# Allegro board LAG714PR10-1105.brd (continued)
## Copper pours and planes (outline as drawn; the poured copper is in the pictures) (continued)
AUD_SPK_R+_C on TOP (solid shape): 26.31,3.2 26.31,2.37 26.26,2.32 25.66,2.32 25.34,2.65 24.51,2.65 23.62,1.76 21.18,1.76 21.08,1.86 21.08,2.51 21.19,2.62 21.29,2.62 21.51,2.66 21.7,2.77 22.42,2.77 22.93,3.28 26.23,3.28
AUD_SPK_R+_C on BOTTOM (solid shape): 17.53,6.2 20.58,6.2 21.41,5.37 21.41,3.11 22.26,2.26 22.26,1.84 21.99,1.57 21.04,1.57 20.28,2.33 20.28,4.8 19.89,5.19 19.88,5.19 19.8,5.27 16.15,5.27 16.12,5.29 16.12,6.66 16.17,6.71 17.02,6.71
AUD_SPK_R- on TOP (solid shape): 27.96,4.06 27.97,4.06 28.1,3.93 31.09,3.93 31.35,3.67 31.35,3.25 31.02,2.92 27.78,2.92 27.3,3.4 26.61,3.4 26.49,3.52 26.49,4.28 26.57,4.36 27.66,4.36
AUD_SPK_R- on TOP (solid shape): 30.55,10.6 30.55,9.27 30.69,9.13 30.74,9.06 30.8,9.01 31.09,8.72 31.15,8.63 31.24,8.57 31.24,8.38 31.12,8.25 30.93,8.25 30.29,8.89 30.29,10.6 30.36,10.66 30.48,10.66
AUD_SPK_R- on IN2 (solid shape): 31.37,4.35 31.37,3.33 31.21,3.17 30.39,3.17 30.1,3.46 30.1,4.6 30.26,4.76 30.96,4.76
AUD_SPK_R- on IN2 (solid shape): 31.12,8.68 31.15,8.64 31.18,8.61 31.18,7.58 30.96,7.36 30.2,7.36 30.07,7.49 30.07,9.08 30.26,9.27 30.52,9.27
AUD_SPK_R-_C on TOP (solid shape): 21.3,4.83 23.47,4.83 24.13,4.17 25.34,4.17 25.48,4.31 26.3,4.31 26.31,4.3 26.31,3.54 26.28,3.51 25.75,3.51 25.68,3.58 22.56,3.58 22.19,3.95 18.67,3.95 18.49,4.14 18.49,5.05 18.56,5.12 21.01,5.12
AUD_SPK_R-_C on BOTTOM (solid shape): 15.74,6.46 15.74,5.13 15.99,4.88 19.64,4.88 19.89,4.64 19.89,4.29 19.42,3.82 16.04,3.82 15.63,4.22 15.63,4.43 15.08,4.99 15.08,6.53 15.2,6.65 15.55,6.65
BST_1.2V on BOTTOM (solid shape): 95.8,137 95.8,136.63 95.83,136.61 95.83,136.52 95.8,136.5 95.8,135.99 95.2,135.38 95.2,133.93 95.14,133.88 95.04,133.88 94.99,133.93 94.99,134.73 94.94,134.78 94.94,136.85 95.11,137.02 95.79,137.02
BST_1.2V_R on BOTTOM (solid shape): 94.41,137 94.41,136.14 94.38,136.11 93.67,136.11 93.44,136.34 92.83,136.34 92.82,136.36 92.82,136.85 92.99,137.02 94.4,137.02
BST_3V on BOTTOM (solid shape): 105.62,138.62 106.78,138.62 106.84,138.55 106.84,138.43 106.78,138.36 106.33,138.36 105.13,137.16 104.24,137.16 104.24,137.86 105.08,138.7 105.54,138.7
BST_5V on BOTTOM (solid shape): 155.99,137.09 157.07,137.09 157.13,137.03 157.13,136.9 157.02,136.79 153.91,136.79 153.81,136.89 153.81,137.4 153.88,137.47 155.61,137.47
BST_+1VALW on BOTTOM (solid shape): 166.47,54.84 166.47,54.65 165.83,54.02 165.83,52.87 166.15,52.56 166.15,51.98 165.26,51.98 165.26,54.46 165.71,54.91 166.4,54.91
BST_+1VALW_R on BOTTOM (solid shape): 166.15,50.59 164.44,50.59 164.31,50.71 164.31,51.2 164.33,51.22 166.15,51.22
BST_VCCSA on BOTTOM (solid shape): 172.06,62.29 171.92,62.15 171.92,62.02 171.87,61.97 171.74,61.97 171.19,61.43 170.32,61.43 170.21,61.53 170.21,61.83 170.34,61.95 170.85,61.95 171.42,62.53 171.42,63.22 172.06,63.22
BST_VCORE1 on BOTTOM: 163.35,76.9 162.54,76.9 162.47,76.83 162.47,76.65 162.52,76.6 163.41,76.6 163.47,76.54 164.63,76.54 164.65,76.56 164.65,77.44 164.63,77.47 163.91,77.47
BST_VCORE1_R on BOTTOM (solid shape): 166.1,77.44 166.1,75.41 166.04,75.34 165.36,75.34 165.32,75.38 165.32,77.38 165.33,77.43 165.36,77.47 166.07,77.47
BST_VCORE2 on BOTTOM: 162.45,98.92 162.16,99.2 161.32,99.2 161.25,99.13 161.25,98.95 161.32,98.87 161.75,98.87 161.75,98.87 161.8,98.87 162.4,98.27 162.4,98.22 162.61,98.01 163.29,98.01 163.31,98.03 163.31,98.89 163.28,98.92
BST_VCORE2_R on BOTTOM (solid shape): 164.73,98.86 164.73,96.92 164.63,96.82 163.99,96.82 163.93,96.88 163.93,98.85 163.99,98.91 164.68,98.91
BST_VGT1 on BOTTOM (solid shape): 140.24,132.65 141.13,132.65 141.19,132.58 141.19,132.39 141.13,132.33 139.99,132.33 139.73,132.08 139.1,132.08 139.1,132.96 139.92,132.96
BST_VGT1_R on BOTTOM (solid shape): 138.34,132.08 137.7,132.08 137.7,134.17 138.34,134.17
HDMI_PLL_GND on TOP (solid shape): 16.77,101.69 16.77,96.16 16.34,95.73 14.62,95.73 14.36,95.99 14.36,99.95 16.16,101.76 16.7,101.76
IR_GND on BOTTOM (solid shape): 212.95,49.08 212.95,48.32 212.89,48.26 211.93,48.26 211.81,48.38 211.81,49.02 211.93,49.14 212.89,49.14
LG_1.2V on BOTTOM (solid shape): 94,133.64 94,133.53 93.92,133.46 93.16,133.46 92.31,134.31 92.31,134.56 92.4,134.65 92.98,134.65
LG_1.2V on IN2 (solid shape): 90.9,138.17 90.9,136.55 90.88,136.52 90.2,136.52 90.08,136.65 90.08,136.96 90.33,137.22 90.33,138.17 90.46,138.3 90.78,138.3
LG_1.2V on IN2 (solid shape): 93.25,134.34 93.25,133.87 93.15,133.76 92.85,133.76 92.25,134.36 91.98,134.36 91.6,134.74 91.6,134.93 91.98,135.31 92.27,135.31
LGATE_CHG on BOTTOM (solid shape): 191.3,45.52 191.3,45.27 191.17,45.14 189.14,45.14 189.01,45.27 189.01,45.59 189.07,45.65 191.17,45.65
LGATE_CHG on BOTTOM (solid shape): 197.58,50.99 198.73,50.99 198.78,50.94 198.78,50.77 198.74,50.73 197.77,50.73 197.52,50.83 197.27,50.73 196.44,50.73 196.31,50.86 196.31,51.11 196.44,51.24 197.33,51.24
LGATE_CHG on IN2 (solid shape): 192.5,45.72 192.5,45.46 192.19,45.14 190.28,45.14 190.15,45.27 190.15,45.52 190.28,45.65 191.55,45.65 191.8,45.91 192.31,45.91
LGATE_CHG on IN2 (solid shape): 197.46,51.11 197.46,50.83 197.32,50.77 197.22,50.67 197.01,50.67 196.38,50.03 196.06,50.03 195.74,50.35 195.74,50.54 196.44,51.24 197.33,51.24
LX_1.2V on TOP (solid shape): 87.28,139.16 87.28,137.56 87.19,137.47 85.63,137.47 85.51,137.6 85.51,139.12 85.63,139.25 87.19,139.25
LX_1.2V on BOTTOM (solid shape): 89.89,140.14 92.93,140.14 92.93,139.06 90.33,139.06 88.74,137.47 84.49,137.47 83.92,138.04 83.92,141.35 84.17,141.6 88.43,141.6
LX_1.2V on BOTTOM (solid shape): 93.44,135.92 93.44,135.67 94.4,134.72 94.4,133.92 94.34,133.87 94.24,133.87 92.74,135.36 92.74,135.89 92.81,135.95 93.42,135.95
LX_1.2V on IN2 (solid shape): 91.09,139.95 91.09,139.5 90.97,139.38 89.19,139.38 89.06,139.5 89.06,139.95 89.25,140.14 90.9,140.14
LX_1.2V on IN2 (solid shape): 93.76,135.89 93.76,135.06 94.08,134.74 94.08,134.49 93.95,134.36 93.7,134.36 93,135.06 93,135.89 93.13,136.01 93.63,136.01
LX_1.8VALW on TOP (solid shape): 163.04,47.98 163.74,47.29 163.74,46.46 163.61,46.33 161.64,46.33 161.39,46.59 161.39,48.68 163.04,48.68
LX_1.8VALW on BOTTOM (solid shape): 163.42,48.05 163.42,47.6 163.8,47.22 165.13,47.22 165.2,47.16 165.2,46.52 165.13,46.46 164.25,46.46 164.12,46.33 164.12,45.63 163.86,45.37 160.89,45.37 160.85,45.41 160.85,48.14 160.89,48.17 163.29,48.17
LX_3V on TOP (solid shape): 107.6,136.33 107.6,134.87 107.54,134.81 105.89,134.81 105.83,134.87 105.83,136.27 106.08,136.52 107.41,136.52
LX_3V on BOTTOM (solid shape): 107.62,138.22 107.62,131.14 107.29,130.81 103.86,130.81 103.09,131.57 103.09,135.25 103.22,135.38 105.38,135.38 106.02,136.01 106.02,137.41 106.9,138.3 107.54,138.3
LX_3V on BOTTOM (solid shape): 106.97,142.17 106.97,141.73 107.16,141.54 107.16,140.52 107.1,140.46 106.97,140.46 106.33,141.09 106.33,141.73 106.46,141.85 106.46,142.24 106.59,142.36 106.78,142.36
LX_3V on IN2 (solid shape): 106.99,142.21 107.02,142.09 107.1,141.99 107.1,139.06 107.64,138.51 107.64,136.81 107.54,136.71 106.63,136.71 106.52,136.81 106.52,138.11 106.08,138.55 106.08,142.17 106.27,142.36 106.84,142.36
LX_5V on TOP (solid shape): 157.77,134.34 157.77,133.15 157.64,133.03 155.48,133.03 155.23,133.28 155.23,134.17 155.48,134.42 157.68,134.42
LX_5V on BOTTOM (solid shape): 157.51,140.33 157.51,139 157.45,138.93 157.26,138.93 157.2,139 157.2,139.63 157.01,139.82 156.56,139.82 156.43,139.95 156.43,140.39 156.5,140.46 157.39,140.46
LX_5V on BOTTOM (solid shape): 157.96,136.65 157.96,135.25 158.53,134.68 160,134.68 160.18,134.5 160.18,132.2 160.05,132.08 155.61,132.08 155.04,132.65 155.04,134.98 155.18,135.12 155.61,135.12 157.26,136.77 157.83,136.77
LX_5V on IN2 (solid shape): 157.64,140.33 157.64,135.19 157.45,135 156.63,135 156.43,135.19 156.43,140.33 156.56,140.46 157.51,140.46
LX_+1VALW on TOP (solid shape): 165.01,56.3 165.01,55.1 164.75,54.84 162.78,54.84 162.78,56.49 164.82,56.49
LX_+1VALW on BOTTOM (solid shape): 167.02,56.96 167.02,55.39 166.91,55.29 165.77,55.29 164.88,54.4 164.88,51.6 164.34,51.6 164.31,51.63 164.31,52.62 163.86,53.07 162,53.07 161.96,53.11 161.96,56.87 162.28,57.19 166.79,57.19
LX_VCCSA on TOP (solid shape): 163.74,63.3 163.74,62.29 163.61,62.16 161.64,62.16 161.39,62.42 161.39,63.5 161.45,63.56 163.48,63.56
LX_VCCSA on BOTTOM (solid shape): 164.25,62.73 166.99,62.73 167.56,63.3 168.25,63.3 168.31,63.24 168.31,62.35 168.06,62.1 168.06,61.34 168.18,61.21 168.94,61.21 169.01,61.15 169.01,61.02 168.88,60.89 167.86,60.89 167.04,61.72 164.05,61.72 163.6,61.26 163.6,60.49 163.11,60 161.13,60 160.88,60.26 160.88,61.46 160.94,61.53 161.9,61.53 161.9,62.42 160.94,62.42 160.88,62.48 160.88,63.43 161.01,63.56 163.42,63.56
LX_VCORE1 on TOP (solid shape): 157.7,80.45 157.7,78.86 157.64,78.8 155.93,78.8 155.86,78.86 155.86,80.32 156.12,80.58 157.58,80.58
LX_VCORE1 on BOTTOM (solid shape): 159.79,85.65 159.79,79.1 159.74,79.05 158.48,79.05 158.28,78.85 158.28,75.1 157.64,75.1 157.18,75.56 154.85,75.56 154.28,76.13 154.28,80.5 156.05,82.27 156.05,83.23 156.37,83.54 158.28,83.54 158.28,84.43 157.32,84.43 157.32,85.75 157.35,85.77 159.67,85.77
LX_VCORE2 on TOP (solid shape): 155.23,102.99 155.23,101.66 154.97,101.4 153.54,101.4 153.45,101.49 153.45,103.12 153.51,103.18 155.04,103.18
LX_VCORE2 on BOTTOM (solid shape): 158.59,102.12 158.59,101.4 158.53,101.34 157.2,101.34 157.07,101.21 157.07,97.34 153.51,97.34 152.56,98.29 152.56,100.58 151.67,100.58 151.67,99.63 150.34,99.63 150.34,102.47 150.72,102.85 157.86,102.85
LX_VGT1 on TOP (solid shape): 146.88,128.98 146.88,127.61 146.59,127.31 145.32,127.31 145.07,127.57 145.07,128.96 145.2,129.09 146.77,129.09
LX_VGT1 on BOTTOM (solid shape): 147.23,133.72 147.23,123.75 146.87,123.39 144.36,123.39 144.18,123.58 144.18,124.58 144.37,124.77 145.45,124.77 145.45,125.66 144.12,125.66 143.86,125.92 143.86,130.17 143.93,130.23 145.2,130.23 145.32,130.36 145.32,134.11 145.39,134.17 146.78,134.17
PHASE_CHG on TOP (solid shape): 187.42,50.22 187.42,48.92 187.19,48.68 185.53,48.68 184.94,49.28 184.94,50.39 185.1,50.55 187.09,50.55
PHASE_CHG on BOTTOM (solid shape): 187.17,50.67 187.17,48.83 188.38,47.62 188.38,44.83 186.03,42.48 180.25,42.48 180.06,42.67 180.06,46.54 180.5,46.99 183.68,46.99 185.01,48.32 185.01,50.41 185.39,50.8 187.04,50.8
PHASE_CHG on BOTTOM (solid shape): 197.77,51.37 198.73,51.37 198.78,51.32 198.78,51.19 198.74,51.15 197.61,51.15 197.39,51.37 196.19,51.37 195.8,50.99 195.3,50.99 195.23,51.05 195.23,51.68 195.42,51.87 197.27,51.87
PHASE_CHG on IN2 (solid shape): 186.91,50.67 186.91,50.35 186.6,50.03 185.14,50.03 184.95,50.22 184.95,50.54 185.2,50.8 186.79,50.8
PHASE_CHG on IN2 (solid shape): 197.46,51.75 197.46,51.49 197.33,51.37 196.25,51.37 196,51.11 195.68,51.11 195.55,51.24 195.55,51.75 195.68,51.87 197.33,51.87
PHASE_VCORE1 on BOTTOM (solid shape): 164.64,76.25 164.64,75.36 164.59,75.31 163.46,75.31 163.17,75.6 162.54,75.6 162.47,75.67 162.47,75.86 162.53,75.92 163.23,75.92 163.58,76.27 164.61,76.27
PHASE_VCORE2 on BOTTOM (solid shape): 162.63,97.72 163.23,97.72 163.23,96.82 162.58,96.82 162.29,97.11 162.29,97.5 161.9,97.9 161.32,97.9 161.26,97.96 161.26,98.15 161.32,98.21 162.14,98.21
PHASE_VGT1 on BOTTOM (solid shape): 140.24,133.66 141.13,133.66 141.19,133.6 141.19,133.41 141.07,133.28 140.31,133.28 140.24,133.22 139.16,133.22 139.1,133.28 139.1,134.17 139.73,134.17
REGOUT on TOP: 21.89,87.7 21.64,87.86 21.35,87.76 20.51,88.61 20.07,88.61 18.96,89.72 18.96,90.74 18.98,90.76 20.84,90.76 20.99,90.61 20.99,90.17 21.18,89.97 21.75,89.97 23.19,88.54 23.19,87.32 23.14,87.27 22.64,87.27 22.21,87.7 21.89,87.7
RING2 on TOP: 31.12,17.38 30.87,17.13 30.67,17.13 30.54,17.13 30.49,17.18 30.49,17.18 30.49,17.31 30.42,17.38 30.42,18.22 30.07,18.57 30.07,19.68 30.09,19.71 31.54,19.71 31.59,19.66 31.59,19.17 31.12,18.7
RING2_R on TOP (solid shape): 18.32,8.5 18.32,7.42 18,7.11 14.32,7.11 14.19,7.23 14.19,7.55 14.83,8.19 16.61,8.19 17.18,8.76 18.07,8.76
RING2_R on IN1 (solid shape): 15.34,8.06 15.34,7.23 15.21,7.11 14.39,7.11 14.26,7.23 14.26,7.49 14.96,8.19 15.21,8.19
RING2_R on IN2 (solid shape): 19.21,9.39 19.21,8.89 18.26,7.93 17.18,7.93 16.99,8.12 16.99,8.57 17.24,8.82 17.62,8.82 18.39,9.58 19.02,9.58
RING2_R on TOP: 31.75,20.12 31.6,19.97 31.06,19.97 30.96,20.07 30.96,20.56 31.05,20.66 31.05,23.51 31.2,23.66 31.59,23.66 31.75,23.5
RING2_R on IN2: 30.91,23.45 30.91,22.58 30.73,22.4 30.73,21.67 31.09,21.31 31.87,21.31 31.96,21.4 31.96,23.49 31.78,23.67 31.13,23.67
SLEEVE on TOP: 30.29,18.09 30.29,17.3 30.08,17.09 30.01,17.09 29.91,17.19 29.91,17.19 29.59,17.5 28.42,18.68 28.42,19.64 28.47,19.69 29.9,19.69 29.94,19.66 29.94,18.44
SLEEVE_R on TOP (solid shape): 15.91,12 15.91,10.73 16.1,10.54 17.56,10.54 17.88,10.85 17.88,11.23 18.07,11.43 18.64,11.43 18.96,11.11 18.96,9.9 18.07,9.01 16.42,9.01 14.77,10.66 14.77,12 14.96,12.19 15.72,12.19
SLEEVE_R on IN1 (solid shape): 15.91,12.95 15.91,11.74 15.78,11.62 14.89,11.62 14.77,11.74 14.77,13.08 14.96,13.27 15.59,13.27
SLEEVE_R on IN2 (solid shape): 18.89,12.12 18.89,10.54 18.58,10.22 18,10.22 17.88,10.35 17.88,12.12 18.07,12.31 18.7,12.31
SLEEVE_R on TOP: 28.13,22.49 28.01,22.61 28.01,23.23 28.32,23.54 28.83,23.54 29.02,23.35 29.02,20.07 28.97,20.02 28.34,20.02 28.13,20.22
SLEEVE_R on IN2: 27.74,23.36 27.74,22.88 27.49,22.63 27.49,22.24 27.92,21.81 28.96,21.81 29.08,21.93 29.08,23.46 28.89,23.65 28.03,23.65
SNB_VCCSA on TOP (solid shape): 163.04,58.54 162.98,58.48 162.09,58.48 162.02,58.54 162.02,59.05 161.32,59.75 161.32,60.76 161.39,60.83 163.04,60.83
SNUB_+1VALW on TOP (solid shape): 167.55,56 167.55,54.99 167.36,54.79 165.45,54.79 165.45,54.8 165.45,56.51 165.52,56.57 166.98,56.57
UG_1.2V on BOTTOM (solid shape): 90.92,141.69 90.92,141.26 90.81,141.16 89.38,141.16 89.19,141.35 89.19,141.66 89.32,141.79 90.81,141.79
UG_1.2V on BOTTOM (solid shape): 94.81,135.86 94.81,133.92 94.76,133.87 94.64,133.87 94.59,133.92 94.59,134.74 94.22,135.11 94.22,135.87 94.29,135.95 94.72,135.95
UG_1.2V on IN2 (solid shape): 91.03,141.6 91.03,141.03 90.97,140.97 89.32,140.97 89.19,141.09 89.19,141.6 89.32,141.73 90.9,141.73
UG_1.2V on IN2 (solid shape): 94.84,136.58 94.84,135 94.71,134.87 94.4,134.87 94.27,135 94.27,136.08 94.08,136.27 94.08,136.58 94.14,136.65 94.78,136.65
UGATE_CHG on BOTTOM (solid shape): 197.14,52.95 197.14,52.75 197.58,52.3 197.58,52.13 197.93,51.79 198.71,51.79 198.78,51.72 198.78,51.61 198.73,51.56 197.77,51.56 197.14,52.19 196.31,52.19 196.31,53.08 196.38,53.14 196.95,53.14
USB20_VCC on BOTTOM (solid shape): 201.52,39.87 201.52,36.3 201.33,36.11 198,36.11 197.86,36.25 197.86,37.66 198.54,38.35 198.54,38.35 198.66,38.47 198.66,39.24 199.49,40.06 201.33,40.06
USB30_VCCA on TOP (solid shape): 19.72,46.41 19.72,44 19.34,43.62 18.04,43.62 17.69,43.98 17.69,46.03 18.32,46.67 19.47,46.67
USB30_VCCA on TOP (solid shape): 24.18,57.68 24.18,56.46 22.01,54.29 21.12,54.29 20.48,54.92 20.48,55.56 21.62,56.7 21.62,57.34 22.13,57.84 24.01,57.84
USB30_VCCA on BOTTOM (solid shape): 24.29,58.73 24.29,56.95 23.89,56.55 17.84,56.55 17.31,56.03 15.72,56.03 15.38,56.37 15.38,58.22 16.17,59 24.02,59
USB30_VCCA on BOTTOM (solid shape): 19.21,44.76 19.21,43.49 19.72,42.98 20.39,42.98 20.61,42.77 20.61,42.48 20.35,42.22 19.97,42.22 19.34,41.59 19.34,38.79 18.07,37.52 18.07,37.4 17.7,37.03 17.7,32.84 16.93,32.06 15.78,32.06 15.27,32.57 15.27,33.59 15.28,33.6 15.28,34.07 15.66,34.45 15.66,37.65 16.93,38.92 16.93,44.38 17.43,44.89 19.08,44.89
N17237617 on TOP (solid shape): 191.93,52.51 191.93,48.62 191.76,48.45 188.73,48.45 188.61,48.57 188.61,50.65 190.66,52.7 191.74,52.7
N17237617 on BOTTOM (solid shape): 191.99,56.89 191.99,48.45 191.93,48.38 188.18,48.38 187.74,48.83 187.74,51.94 187.17,52.51 187.17,54.67 187.74,54.67 187.74,56.7 187.17,56.7 187.17,57.53 187.42,57.78 191.11,57.78
N17415515 on BOTTOM (solid shape): 79.36,147.12 79.66,146.96 79.96,147.12 83.09,147.12 83.85,146.36 83.85,143.19 83.6,142.94 76.36,142.94 76.04,143.25 76.04,146.81 76.36,147.12
N21222441 on BOTTOM (solid shape): 198.78,49.73 198.78,49.6 198.73,49.55 197.93,49.55 197.01,48.64 197.01,45.33 196.95,45.27 195.93,45.27 195.87,45.33 195.87,48.57 196.06,48.76 196.59,48.76 197.29,49.46 197.42,49.54 197.5,49.67 197.61,49.78 198.73,49.78
N21242279 on TOP (solid shape): 183.93,64.07 183.93,63.18 182.91,62.16 182.91,59.62 182.53,59.24 179.74,59.24 179.49,59.49 179.49,62.29 179.74,62.54 181.14,62.54 181.64,63.05 181.64,64.07 181.77,64.19 183.8,64.19
N21269026 on TOP (solid shape): 158.53,103.21 158.53,102.48 158.47,102.42 157.45,102.42 157.26,102.23 157.26,101.47 157.2,101.4 156.18,101.4 156.12,101.47 156.12,103.09 156.26,103.23 158.5,103.23
N21273981 on TOP (solid shape): 146.85,132.65 146.85,130.7 146.76,130.61 145.18,130.61 145.16,130.64 145.16,132.61 145.32,132.77 146.72,132.77
N21380741 on BOTTOM (solid shape): 160.69,135.31 161.77,135.31 161.83,135.25 161.83,134.42 161.77,134.36 160.75,134.36 159.29,135.82 158.66,135.82 158.53,135.95 158.53,136.65 158.66,136.77 159.23,136.77
N21389189 on TOP (solid shape): 171.91,47.5 171.91,46.49 171.69,46.27 170.28,46.27 170.13,46.12 169.07,46.12 168.82,46.37 168.82,47.6 168.94,47.73 171.68,47.73
N21389189 on BOTTOM (solid shape): 171.91,47.5 171.91,46.12 171.74,45.95 167.41,45.95 167.36,46.01 167.36,47.16 167.42,47.22 168.5,47.22 169.01,47.73 171.68,47.73
N28484451 on TOP: 121.11,144.14 119.99,144.14 119.67,143.82 119.67,141.79 119.86,141.6 121.1,141.6 121.24,141.73 121.24,144.02
N28714564 on BOTTOM (solid shape): 195.61,54.35 195.61,53.53 195.55,53.46 194.85,53.46 194.73,53.34 194.73,52.07 194.92,51.87 194.92,51.01 194.89,50.99 194.34,50.99 194.28,51.05 194.28,54.16 194.53,54.41 195.55,54.41
N28714606 on BOTTOM (solid shape): 196.19,53.08 196.19,52.19 196.06,52.07 195.04,52.07 194.92,52.19 194.92,53.14 194.98,53.21 196.06,53.21
N28714606 on BOTTOM (solid shape): 187.17,52 187.17,51.14 187.02,50.99 186.22,50.99 186.03,51.18 186.03,52 186.15,52.13 187.04,52.13
N28714606 on IN2 (solid shape): 187.99,52.07 187.99,51.56 187.87,51.43 186.28,51.43 186.03,51.68 186.03,52.07 186.15,52.19 187.87,52.19
N28714606 on IN2 (solid shape): 196.19,53.08 196.19,52.19 196.06,52.07 194.92,52.07 194.73,52.26 194.73,52.76 195.17,53.21 196.06,53.21
N28714612 on BOTTOM (solid shape): 197.9,53.73 197.9,53.12 198.02,52.99 198.02,52.45 198.28,52.19 198.73,52.19 198.79,52.13 198.79,52 198.73,51.94 197.96,51.94 197.75,52.15 197.75,52.37 197.33,52.79 197.33,53.21 197.14,53.4 196.31,53.4 196.25,53.46 196.25,54.35 196.31,54.41 197.21,54.41
N28714617 on TOP (solid shape): 188.38,62.42 188.38,56.19 187.55,55.37 185.71,55.37 185.71,55.94 187.23,55.94 187.23,56.64 185.71,56.64 185.71,57.34 185.07,57.97 183.68,57.97 183.41,58.24 183.41,62.3 183.78,62.67 188.12,62.67
N28714693 on BOTTOM (solid shape): 178.79,53.14 178.79,52.13 179.04,51.87 180.37,51.87 180.82,52.32 180.82,53.14 181.07,53.4 183.93,53.4 184.12,53.21 184.12,51.56 183.92,51.35 183.92,48.71 183.85,48.65 179.98,48.65 178.66,49.97 177.96,49.97 177.33,50.6 177.33,52.32 176.69,52.32 176.69,52.29 176.69,50.79 176.56,50.67 176.06,50.67 175.87,50.86 175.87,53.02 176.25,53.4 178.53,53.4
N28714782 on TOP (solid shape): 188.44,47.18 188.44,46.29 188.31,46.16 185.71,46.16 185.64,46.22 185.64,47.24 185.71,47.3 188.31,47.3
N28714793 on BOTTOM (solid shape): 180.27,53.25 180.27,52.23 180.17,52.13 179.1,52.13 178.98,52.26 178.98,53.14 179.23,53.4 180.12,53.4
N45789065 on TOP (solid shape): 158.59,77.08 158.59,76.2 158.53,76.13 155.99,76.13 155.93,76.2 155.93,77.2 155.98,77.25 158.43,77.25
N47714748 on TOP (solid shape): 90.84,139.12 90.84,138.62 90.71,138.49 90.2,138.49 89.95,138.23 89.95,137.57 89.85,137.47 88.88,137.47 88.81,137.55 88.81,139.16 88.9,139.25 90.71,139.25
N47719295 on TOP (solid shape): 91.94,133.07 91.94,132.19 91.86,132.11 90.88,132.11 90.68,132.31 90.68,133 90.77,133.09 91.92,133.09
N47719295 on BOTTOM (solid shape): 92.53,132.48 93.95,132.48 93.99,132.44 93.99,132.3 93.95,132.27 93.02,132.27 92.82,132.06 90.93,132.06 90.68,132.31 90.68,133 90.77,133.09 91.92,133.09
N47887852 on TOP (solid shape): 163.93,45.83 163.93,45.19 163.74,45 161.39,45 161.39,46.02 163.74,46.02

Small or netless copper shapes (teardrops, artwork), in the pictures only: 219 on TOP, 134 on BOTTOM

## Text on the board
Ref Des/Silkscreen Bottom: H12 | M2L4
User.Comments: LAG714P | 2019-11-06 | 2018-11-06 | Chris_Wang | EDI72
Ref Des/Silkscreen Top: A
User.40: trace Width | 7.6mil | 5.9mil | 42 ohm
User.41: FIGURE | SIZE | 8.0 | 22.0 | 28.0 | 35.0 | 118.0 | 126.0 | 130.0 | 146.0 | 157.0 | 197.0 | 43.0 | 63.0 | 220.0 | 55.0x24.0 | 63.0x24.0 | 63.0x35.0 | 71.0x31.0 | 102.0x31.0 | 157.0x118.0 | 157.0x146.0 | DRILL CHART: TOP to BOTTOM | ALL UNITS ARE IN MILS | TOLERANCE | +3.0/-3.0 | +2.0/-2.0 | PLATED | NON-PLATED | QTY | 4380 | 19 | 18 | 8 | 6 | 1 | 4 | 7
